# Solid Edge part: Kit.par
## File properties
Dokumentum tartalom típus: 0
Last saved by: psaghy
Revision: 77
Sűrűség: 0,000 kg/m^3
Pontosság: 0,990
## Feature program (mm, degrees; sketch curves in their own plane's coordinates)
base feature "unnamed BaseFeature 1"
sketch for "Furat_1" plane through (0, 0, 37) normal (0, 0, 1) x-axis (0, -1, 0)
  hole centre (-19, 19) bore radius 2.4585
hole "Furat_1" nominal diameter 6 finite  VBottomAngle = 118 deg; ThreadDepth = 16 mm
sketch for "unnamed Hole 1" plane through (0, 0, 37) normal (0, 0, 1) x-axis (0, -1, 0)
  hole centre (-19, -19) bore radius 2.4585
hole "unnamed Hole 1" finite
sketch for "unnamed Hole 2" plane through (0, 0, 37) normal (0, 0, 1) x-axis (0, -1, 0)
  hole centre (19, -19) bore radius 2.4585
hole "unnamed Hole 2" finite
sketch for "unnamed Hole 3" plane through (0, 0, 37) normal (0, 0, 1) x-axis (0, -1, 0)
  hole centre (19, 19) bore radius 2.4585
hole "unnamed Hole 3" finite
pattern "unnamed Pattern 1" of "Furat_1", "unnamed Hole 1", "unnamed Hole 2", "unnamed Hole 3"
sketch for "Furat_5" plane through (27.25, 0, 19.2488) normal (1, 0, 0) x-axis (0, 0, -1)
hole "Furat_5" diameter 13.157 finite  ThreadDepth = 12 mm
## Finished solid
Body 1: solid body, 370 faces, 887 edges, 570 vertices, 3 internal voids.
  Faces by surface: plane 146, cylinder 97, cone 43, torus 38, spline 31, sphere 9, swept 6
  Edges by curve: line 365, circle 310, curve on surface 184, spline 28
Bounding box of the edges (mm; curved faces can reach further): 54.500 x 54.500 x 53.000, from (-27.25, -27.25, 6) to (27.25, 27.25, 59).
Cylindrical faces by radius (mm): R0.2344 x1, R0.4113 x1, R0.4771 x1, R0.5 x7, R0.5094 x1, R0.5226 x1, R0.5534 x1, R0.6836 x1, R0.7041 x1, R0.7049 x1, R0.7519 x1, R0.7795 x1, R0.7904 x1, R0.8051 x1, R0.824 x1, R0.8903 x1, R0.9421 x1, R0.9541 x2, R1 x12, R1.0216 x1, R1.0284 x1, R1.25 x1, R1.2857 x1, R2.4585 x8, R3 x4, R3.1 x4, R3.5 x1, R4.95 x1, R5 x7, R5.15 x4, R5.72 x1, R5.7225 x1, R7.5 x1, R8 x1, R8.25 x4, R8.3 x1, R8.4 x1, R8.4236 x1, R8.7 x1, R10 x2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
Conical faces (half-angle, radius in mm at the cone's reference point): 1.6538 deg R9.75 x1, 3.5477 deg R10.7454 x1, 5.762 deg R8.4 x1, 11.1239 deg R8.0056 x1, 15 deg R16.1406 x1, 15.3654 deg R8.7214 x1, 19.3654 deg R9.1921 x1, 25.0169 deg R12.31 x1, 29.0546 deg R23.75 x4, 30 deg R5.1443 x1, 30 deg R9.8557 x2, 30 deg R10.1443 x1, 30 deg R17 x1, 45 deg R2.75 x1, 45 deg R2.825 x1, 45 deg R3.25 x8, 45 deg R4.85 x8, 45 deg R6.72 x1, 45 deg R8.15 x2, 45 deg R13.25 x1, 59 deg R2.4585 x4
Toroidal faces (ring radius, tube radius in mm): R0.9686 r0.5 x1, R1.4708 r0.5006 x3, R3.3 r0.3 x4, R4.7 r0.3 x1, R4.95 r0.2 x4, R5.65 r0.5 x4, R8.3 r0.3 x1, R8.3085 r0.3 x1, R8.75 r0.5 x2, R9.4279 r0.25 x1, R9.5 r0.5 x1, R10.2464 r0.5 x1, R12.8 r0.2 x1, R14.5 r2 x1, R15.3663 r0.5 x1, R18 r0.5 x1, R22 r1 x3, R26.5 r1 x6, R27.7942 r0.5 x1
Spherical faces by radius (mm): R0.5 x3, R1 x6
Planar faces by outward normal: +x 26, +y 10, +z 32, -x 5, -y 9, -z 22, oblique 42
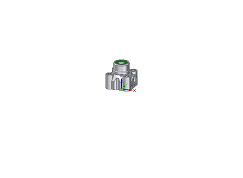
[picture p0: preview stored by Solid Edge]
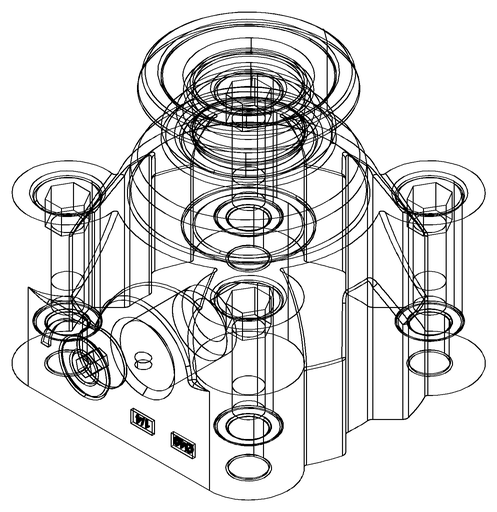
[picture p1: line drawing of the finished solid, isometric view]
